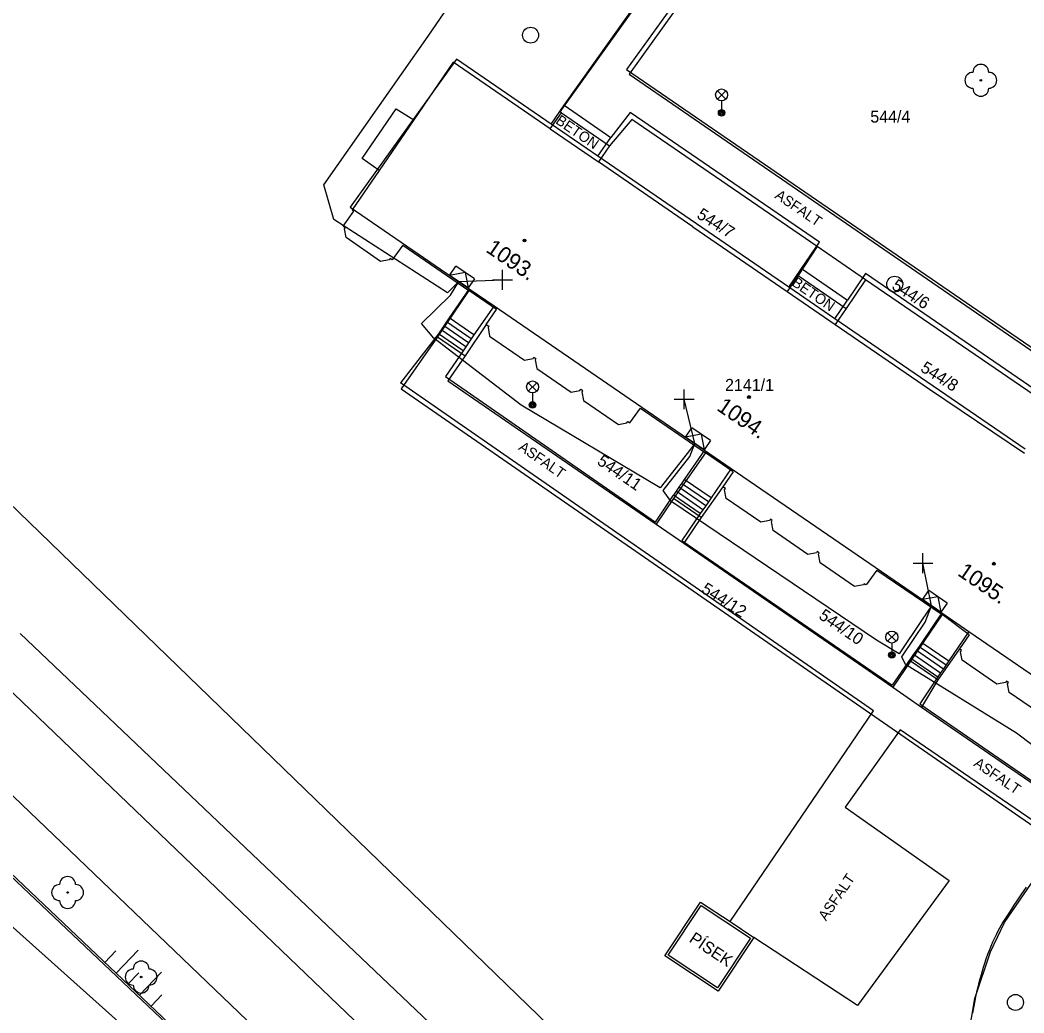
# Model space of a CAD drawing. Extents: x -540150 to -533593, y -1185082 to -1180066.
# Drawn here: x -536687.4 to -536624.5, y -1184506.1 to -1184443.9 of the extents above; entities that cross this region are included whole.
import ezdxf

# ---------------------------------------------------------------- set-up
doc = ezdxf.new("R2010")
doc.units = 0
for name, color, linetype in [('KN_HRAN_K_Ú', 7, 'Continuous'), ('KN_HRAN_PARCEL', 7, 'Continuous'), ('KN_PARC_Č', 7, 'Continuous'), ('KN_VKP_HRAN_', 7, 'Continuous'), ('Vrstva 1', 7, 'Continuous'), ('Vrstva 10', 7, 'Continuous'), ('Vrstva 11', 7, 'Continuous'), ('Vrstva 14', 7, 'Continuous'), ('Vrstva 15', 7, 'Continuous'), ('Vrstva 22', 7, 'Continuous'), ('Vrstva 23', 7, 'Continuous'), ('Vrstva 27', 7, 'Continuous'), ('Vrstva 31', 7, 'Continuous'), ('Vrstva 33', 7, 'Continuous'), ('Vrstva 34', 7, 'Continuous'), ('Vrstva 39', 7, 'Continuous'), ('Vrstva 40', 7, 'Continuous'), ('Vrstva 41', 7, 'Continuous'), ('Vrstva 47', 7, 'Continuous'), ('Vrstva 5', 7, 'Continuous'), ('Vrstva 59', 7, 'Continuous'), ('Vrstva 9', 7, 'Continuous')]:
    doc.layers.add(name, color=color, linetype=linetype)

# ---------------------------------------------------------------- blocks, each defined once
blk = doc.blocks.new('NN800')
at = {"layer": 'Vrstva 1'}
for points in [[(-0.442, 0.442), (0.442, -0.442)], [(-0.442, -0.442), (0.442, 0.442)]]:
    blk.add_lwpolyline(points, dxfattribs=at)
blk = doc.blocks.new('NN630')
at = {"layer": 'Vrstva 9'}
for points in [[(-0.003, -0.7), (-0.703, 0)], [(-0.703, -0.7), (-0.703, 0), (0.697, 0), (0.697, -0.7)], [(-0.003, -0.7), (0.697, 0)], [(-0.703, -0.7), (0.697, -0.7)]]:
    blk.add_lwpolyline(points, dxfattribs=at)

msp = doc.modelspace()

# ---------------------------------------------------------------- linework, layer by layer
at = {"layer": 'KN_HRAN_K_Ú'}
msp.add_line((-536697.202, -1184477.151), (-536639.212, -1184532.701), dxfattribs=at)
at = {"layer": 'KN_HRAN_PARCEL'}
for p, q in [((-536653.562, -1184449.641), (-536639.962, -1184430.591)), ((-536638.172, -1184431.831), (-536649.252, -1184447.281)), ((-536660.272, -1184446.531), (-536662.732, -1184450.131)), ((-536654.192, -1184450.701), (-536660.272, -1184446.531)), ((-536649.252, -1184447.281), (-536620.072, -1184467.331)), ((-536665.982, -1184452.571), (-536663.842, -1184449.451)), ((-536663.842, -1184449.451), (-536662.732, -1184450.131)), ((-536654.192, -1184450.701), (-536653.492, -1184449.691)), ((-536653.492, -1184449.691), (-536653.562, -1184449.641)), ((-536653.492, -1184449.691), (-536650.472, -1184451.761)), ((-536649.082, -1184450.111), (-536650.472, -1184451.761)), ((-536637.462, -1184458.071), (-536649.082, -1184450.111)), ((-536650.472, -1184451.761), (-536651.172, -1184452.781)), ((-536664.912, -1184453.311), (-536665.982, -1184452.571)), ((-536645.252, -1184456.841), (-536651.172, -1184452.781)), ((-536664.912, -1184453.311), (-536666.602, -1184455.791)), ((-536667.162, -1184456.811), (-536666.492, -1184455.861)), ((-536666.602, -1184455.791), (-536666.492, -1184455.861)), ((-536667.042, -1184456.901), (-536667.162, -1184456.811)), ((-536667.092, -1184456.981), (-536667.042, -1184456.901)), ((-536645.252, -1184456.841), (-536639.342, -1184460.891)), ((-536666.992, -1184457.521), (-536667.092, -1184456.981)), ((-536664.822, -1184459.021), (-536666.992, -1184457.521)), ((-536663.422, -1184457.991), (-536664.102, -1184458.921)), ((-536663.422, -1184457.991), (-536659.292, -1184460.831)), ((-536637.462, -1184458.071), (-536638.662, -1184459.901)), ((-536634.422, -1184460.161), (-536637.462, -1184458.071)), ((-536664.222, -1184458.831), (-536664.282, -1184458.911)), ((-536664.102, -1184458.921), (-536664.222, -1184458.831)), ((-536664.282, -1184458.911), (-536664.822, -1184459.021)), ((-536638.662, -1184459.901), (-536639.342, -1184460.891)), ((-536634.422, -1184460.161), (-536635.652, -1184461.961)), ((-536622.662, -1184468.231), (-536634.422, -1184460.161)), ((-536659.292, -1184460.831), (-536661.252, -1184463.741)), ((-536635.652, -1184461.961), (-536636.332, -1184462.961)), ((-536658.202, -1184462.961), (-536659.522, -1184464.931)), ((-536658.202, -1184462.961), (-536658.032, -1184463.081)), ((-536658.032, -1184463.081), (-536658.092, -1184463.161)), ((-536658.092, -1184463.161), (-536657.992, -1184463.701)), ((-536636.332, -1184462.961), (-536630.412, -1184467.031)), ((-536661.252, -1184463.741), (-536663.532, -1184467.001)), ((-536661.252, -1184463.741), (-536659.522, -1184464.931)), ((-536657.992, -1184463.701), (-536655.812, -1184465.201)), ((-536659.522, -1184464.931), (-536660.612, -1184466.491)), ((-536655.812, -1184465.201), (-536655.272, -1184465.091)), ((-536655.272, -1184465.091), (-536655.212, -1184465.011)), ((-536655.212, -1184465.011), (-536655.092, -1184465.101)), ((-536655.092, -1184465.101), (-536655.142, -1184465.181)), ((-536655.142, -1184465.181), (-536655.042, -1184465.721)), ((-536655.042, -1184465.721), (-536652.872, -1184467.211)), ((-536663.532, -1184467.001), (-536622.332, -1184495.521)), ((-536660.612, -1184466.491), (-536647.562, -1184475.491)), ((-536652.872, -1184467.211), (-536652.332, -1184467.111)), ((-536652.332, -1184467.111), (-536652.272, -1184467.031)), ((-536652.272, -1184467.031), (-536652.212, -1184467.071)), ((-536652.212, -1184467.071), (-536652.152, -1184467.121)), ((-536652.152, -1184467.121), (-536652.202, -1184467.201)), ((-536652.202, -1184467.201), (-536652.102, -1184467.741)), ((-536630.412, -1184467.031), (-536624.472, -1184471.041)), ((-536652.102, -1184467.741), (-536649.922, -1184469.231)), ((-536649.202, -1184469.131), (-536648.542, -1184468.211)), ((-536648.542, -1184468.211), (-536644.452, -1184471.021)), ((-536649.922, -1184469.231), (-536649.382, -1184469.131)), ((-536649.382, -1184469.131), (-536649.332, -1184469.051)), ((-536649.332, -1184469.051), (-536649.202, -1184469.131)), ((-536644.452, -1184471.021), (-536646.462, -1184473.881)), ((-536633.292, -1184527.221), (-536690.882, -1184471.461)), ((-536643.372, -1184473.141), (-536644.732, -1184475.071)), ((-536643.212, -1184473.251), (-536643.372, -1184473.141)), ((-536643.272, -1184473.331), (-536643.212, -1184473.251)), ((-536646.462, -1184473.881), (-536647.562, -1184475.491)), ((-536643.172, -1184473.871), (-536643.272, -1184473.331)), ((-536640.992, -1184475.361), (-536643.172, -1184473.871)), ((-536644.732, -1184475.071), (-536645.822, -1184476.681)), ((-536640.392, -1184475.181), (-536640.452, -1184475.261)), ((-536640.272, -1184475.261), (-536640.392, -1184475.181)), ((-536647.562, -1184475.491), (-536645.822, -1184476.681)), ((-536640.452, -1184475.261), (-536640.992, -1184475.361)), ((-536640.322, -1184475.351), (-536640.272, -1184475.261)), ((-536640.222, -1184475.891), (-536640.322, -1184475.351)), ((-536638.052, -1184477.381), (-536640.222, -1184475.891)), ((-536645.822, -1184476.681), (-536632.722, -1184485.711)), ((-536637.512, -1184477.281), (-536638.052, -1184477.381)), ((-536637.452, -1184477.201), (-536637.512, -1184477.281)), ((-536637.392, -1184477.241), (-536637.452, -1184477.201)), ((-536637.332, -1184477.281), (-536637.392, -1184477.241)), ((-536637.382, -1184477.371), (-536637.332, -1184477.281)), ((-536637.282, -1184477.911), (-536637.382, -1184477.371)), ((-536635.112, -1184479.401), (-536637.282, -1184477.911)), ((-536633.712, -1184478.371), (-536634.382, -1184479.301)), ((-536633.712, -1184478.371), (-536629.622, -1184481.141)), ((-536634.562, -1184479.301), (-536635.112, -1184479.401)), ((-536634.512, -1184479.221), (-536634.562, -1184479.301)), ((-536634.382, -1184479.301), (-536634.512, -1184479.221)), ((-536629.622, -1184481.141), (-536631.612, -1184484.071)), ((-536648.792, -1184519.081), (-536687.422, -1184482.341)), ((-536628.542, -1184483.311), (-536629.892, -1184485.251)), ((-536628.422, -1184483.401), (-536628.542, -1184483.311)), ((-536628.472, -1184483.481), (-536628.422, -1184483.401)), ((-536628.372, -1184484.021), (-536628.472, -1184483.481)), ((-536631.612, -1184484.071), (-536632.722, -1184485.711)), ((-536626.202, -1184485.511), (-536628.372, -1184484.021)), ((-536629.892, -1184485.251), (-536630.932, -1184486.951)), ((-536632.722, -1184485.711), (-536630.932, -1184486.951)), ((-536625.652, -1184485.411), (-536626.202, -1184485.511)), ((-536625.602, -1184485.331), (-536625.652, -1184485.411)), ((-536625.472, -1184485.421), (-536625.602, -1184485.331)), ((-536625.532, -1184485.501), (-536625.472, -1184485.421)), ((-536625.432, -1184486.041), (-536625.532, -1184485.501)), ((-536623.252, -1184487.531), (-536625.432, -1184486.041)), ((-536630.932, -1184486.951), (-536621.042, -1184493.761)), ((-536691.382, -1184494.351), (-536675.902, -1184509.001)), ((-536625.722, -1184500.451), (-536622.332, -1184495.521)), ((-536626.592, -1184502.301), (-536625.722, -1184500.451)), ((-536627.582, -1184505.221), (-536626.592, -1184502.301)), ((-536628.102, -1184508.251), (-536627.582, -1184505.221))]:
    msp.add_line(p, q, dxfattribs=at)
at = {"layer": 'KN_VKP_HRAN_'}
for p, q in [((-536662.732, -1184450.131), (-536664.912, -1184453.311)), ((-536654.192, -1184450.701), (-536651.172, -1184452.781)), ((-536638.662, -1184459.901), (-536635.652, -1184461.961)), ((-536657.562, -1184462.021), (-536659.292, -1184460.831)), ((-536639.342, -1184460.891), (-536636.332, -1184462.961)), ((-536658.202, -1184462.961), (-536657.562, -1184462.021)), ((-536642.722, -1184472.211), (-536644.452, -1184471.021)), ((-536642.722, -1184472.211), (-536643.372, -1184473.141)), ((-536644.732, -1184475.071), (-536646.462, -1184473.881)), ((-536627.932, -1184482.421), (-536629.622, -1184481.141)), ((-536627.932, -1184482.421), (-536628.542, -1184483.311)), ((-536629.892, -1184485.251), (-536631.612, -1184484.071))]:
    msp.add_line(p, q, dxfattribs=at)
at = {"layer": 'Vrstva 10'}
for p, q in [((-536647.007, -1184502.544), (-536644.772, -1184499.181)), ((-536646.799, -1184502.502), (-536644.73, -1184499.389)), ((-536644.73, -1184499.389), (-536641.64, -1184501.443)), ((-536641.64, -1184501.443), (-536643.709, -1184504.556)), ((-536641.432, -1184501.401), (-536643.667, -1184504.764)), ((-536643.667, -1184504.764), (-536647.007, -1184502.544)), ((-536643.709, -1184504.556), (-536646.799, -1184502.502))]:
    msp.add_line(p, q, dxfattribs=at)
for points in [[(-536624.359, -1184498.235), (-536624.696, -1184498.726), (-536624.947, -1184499.098), (-536625.135, -1184499.38), (-536625.414, -1184499.807), (-536625.692, -1184500.241), (-536625.814, -1184500.438), (-536625.927, -1184500.631), (-536626.033, -1184500.82), (-536626.132, -1184501.004)], [(-536644.772, -1184499.181), (-536642.922, -1184500.391), (-536641.432, -1184501.401)], [(-536626.311, -1184501.359), (-536626.391, -1184501.529), (-536626.467, -1184501.696), (-536626.537, -1184501.858), (-536626.604, -1184502.016), (-536626.666, -1184502.17), (-536626.781, -1184502.47), (-536626.883, -1184502.753), (-536626.973, -1184503.02), (-536627.053, -1184503.272), (-536627.125, -1184503.509), (-536627.189, -1184503.732), (-536627.246, -1184503.942), (-536627.298, -1184504.139), (-536627.39, -1184504.51), (-536627.465, -1184504.836), (-536627.527, -1184505.121), (-536627.579, -1184505.371), (-536627.665, -1184505.81), (-536627.725, -1184506.138)], [(-536626.132, -1184501.004), (-536626.224, -1184501.183), (-536626.311, -1184501.359)]]:
    msp.add_lwpolyline(points, dxfattribs=at)
at = {"layer": 'Vrstva 11'}
for p, q in [((-536653.322, -1184449.221), (-536639.952, -1184430.391)), ((-536638.212, -1184431.481), (-536649.422, -1184446.991)), ((-536649.422, -1184446.991), (-536620.042, -1184467.151)), ((-536654.136, -1184450.407), (-536653.322, -1184449.221)), ((-536653.322, -1184449.221), (-536650.402, -1184451.241)), ((-536649.192, -1184449.671), (-536650.402, -1184451.241)), ((-536637.312, -1184457.811), (-536649.192, -1184449.671)), ((-536651.208, -1184452.416), (-536650.402, -1184451.241)), ((-536638.447, -1184459.464), (-536637.312, -1184457.811)), ((-536639.244, -1184460.626), (-536638.447, -1184459.464)), ((-536638.447, -1184459.464), (-536635.552, -1184461.451)), ((-536634.432, -1184459.781), (-536635.552, -1184461.451)), ((-536622.492, -1184467.961), (-536634.432, -1184459.781)), ((-536636.349, -1184462.613), (-536635.552, -1184461.451)), ((-536658.971, -1184463.626), (-536660.522, -1184462.561)), ((-536659.311, -1184464.121), (-536660.862, -1184463.056)), ((-536659.141, -1184463.874), (-536660.692, -1184462.809)), ((-536661.202, -1184463.551), (-536663.572, -1184466.631)), ((-536659.651, -1184464.616), (-536661.202, -1184463.551)), ((-536659.481, -1184464.368), (-536661.032, -1184463.303)), ((-536659.651, -1184464.616), (-536660.752, -1184466.221)), ((-536660.752, -1184466.221), (-536647.592, -1184475.361)), ((-536633.922, -1184487.181), (-536663.572, -1184466.631)), ((-536644.108, -1184473.837), (-536645.793, -1184472.681)), ((-536644.447, -1184474.332), (-536646.132, -1184473.176)), ((-536644.277, -1184474.084), (-536645.962, -1184472.928)), ((-536647.592, -1184475.361), (-536646.472, -1184473.671)), ((-536644.787, -1184474.827), (-536646.472, -1184473.671)), ((-536644.617, -1184474.579), (-536646.302, -1184473.423)), ((-536644.787, -1184474.827), (-536645.942, -1184476.511)), ((-536645.942, -1184476.511), (-536632.752, -1184485.591)), ((-536631.075, -1184483.147), (-536629.382, -1184484.308)), ((-536630.906, -1184482.9), (-536629.213, -1184484.061)), ((-536631.585, -1184483.89), (-536632.752, -1184485.591)), ((-536631.585, -1184483.89), (-536629.892, -1184485.051)), ((-536631.415, -1184483.642), (-536629.722, -1184484.803)), ((-536631.245, -1184483.395), (-536629.552, -1184484.556)), ((-536629.892, -1184485.051), (-536631.032, -1184486.751)), ((-536631.032, -1184486.751), (-536620.952, -1184493.691)), ((-536642.922, -1184500.391), (-536633.922, -1184487.181)), ((-536632.252, -1184488.381), (-536635.712, -1184493.221)), ((-536622.192, -1184495.281), (-536632.252, -1184488.381)), ((-536635.712, -1184493.221), (-536629.182, -1184497.831)), ((-536629.182, -1184497.831), (-536634.932, -1184505.661)), ((-536634.932, -1184505.661), (-536641.432, -1184501.401))]:
    msp.add_line(p, q, dxfattribs=at)
for points in [[(-536659.268, -1184460.732), (-536660.522, -1184462.561), (-536660.692, -1184462.809), (-536660.862, -1184463.056), (-536661.032, -1184463.303), (-536661.202, -1184463.551)], [(-536657.716, -1184461.796), (-536658.971, -1184463.626), (-536659.141, -1184463.874), (-536659.311, -1184464.121), (-536659.481, -1184464.368), (-536659.651, -1184464.616)], [(-536644.531, -1184470.842), (-536645.793, -1184472.681), (-536645.962, -1184472.928), (-536646.132, -1184473.176), (-536646.302, -1184473.423), (-536646.472, -1184473.671)], [(-536642.846, -1184471.998), (-536644.108, -1184473.837), (-536644.277, -1184474.084), (-536644.447, -1184474.332), (-536644.617, -1184474.579), (-536644.787, -1184474.827)], [(-536629.641, -1184481.056), (-536630.906, -1184482.9), (-536631.075, -1184483.147), (-536631.245, -1184483.395), (-536631.415, -1184483.642), (-536631.585, -1184483.89)], [(-536627.948, -1184482.218), (-536629.213, -1184484.061), (-536629.382, -1184484.308), (-536629.552, -1184484.556), (-536629.722, -1184484.803), (-536629.892, -1184485.051)]]:
    msp.add_lwpolyline(points, dxfattribs=at)
at = {"layer": 'Vrstva 14'}
for p, q in [((-536695.692, -1184485.041), (-536670.862, -1184508.831)), ((-536673.732, -1184510.911), (-536697.702, -1184488.171))]:
    msp.add_line(p, q, dxfattribs=at)
at = {"layer": 'Vrstva 15'}
for p, q in [((-536682.116, -1184502.958), (-536681.428, -1184502.232)), ((-536681.39, -1184503.646), (-536680.014, -1184502.195)), ((-536680.665, -1184504.334), (-536679.977, -1184503.609)), ((-536679.94, -1184505.022), (-536678.563, -1184503.571)), ((-536679.214, -1184505.71), (-536678.526, -1184504.985))]:
    msp.add_line(p, q, dxfattribs=at)
at = {"layer": 'Vrstva 22'}
for centre in [(-536627.202, -1184447.661), (-536684.442, -1184498.581), (-536679.832, -1184503.881)]:
    msp.add_circle(centre, 0.05, dxfattribs=at)
for centre, start, end in [((-536627.202, -1184447.161), 0, 180), ((-536627.702, -1184447.661), 90, 270), ((-536626.702, -1184447.661), 270, 90), ((-536627.202, -1184448.161), 180, 0), ((-536684.442, -1184498.081), 0, 180), ((-536684.942, -1184498.581), 90, 270), ((-536683.942, -1184498.581), 270, 90), ((-536684.442, -1184499.081), 180, 0), ((-536679.832, -1184503.381), 0, 180), ((-536680.332, -1184503.881), 90, 270), ((-536679.332, -1184503.881), 270, 90), ((-536679.832, -1184504.381), 180, 0)]:
    msp.add_arc(centre, 0.5, start, end, dxfattribs=at)
at = {"layer": 'Vrstva 23'}
msp.add_line((-536699.382, -1184490.491), (-536674.972, -1184512.291), dxfattribs=at)
at = {"layer": 'Vrstva 27'}
for centre in [(-536655.422, -1184444.831), (-536632.602, -1184460.441), (-536625.032, -1184505.471)]:
    msp.add_circle(centre, 0.5, dxfattribs=at)
at = {"layer": 'Vrstva 33'}
for p, q in [((-536643.717, -1184448.841), (-536643.187, -1184448.311)), ((-536643.717, -1184448.311), (-536643.187, -1184448.841)), ((-536643.452, -1184448.951), (-536643.452, -1184449.701)), ((-536655.567, -1184467.151), (-536655.037, -1184466.621)), ((-536655.567, -1184466.621), (-536655.037, -1184467.151)), ((-536655.302, -1184467.261), (-536655.302, -1184468.011)), ((-536633.047, -1184482.831), (-536632.517, -1184482.301)), ((-536633.047, -1184482.301), (-536632.517, -1184482.831)), ((-536632.782, -1184482.941), (-536632.782, -1184483.691))]:
    msp.add_line(p, q, dxfattribs=at)
for centre, radius in [((-536643.452, -1184448.576), 0.375), ((-536643.452, -1184449.701), 0.2), ((-536643.452, -1184449.701), 0.145), ((-536643.452, -1184449.701), 0.0876), ((-536655.302, -1184466.886), 0.375), ((-536655.302, -1184468.011), 0.2), ((-536655.302, -1184468.011), 0.145), ((-536655.302, -1184468.011), 0.0876), ((-536632.782, -1184482.566), 0.375), ((-536632.782, -1184483.691), 0.2), ((-536632.782, -1184483.691), 0.145), ((-536632.782, -1184483.691), 0.0876)]:
    msp.add_circle(centre, radius, dxfattribs=at)
at = {"layer": 'Vrstva 39'}
for centre, radius in [((-536655.802, -1184457.706), 0.09), ((-536655.802, -1184457.706), 0.0398), ((-536641.735, -1184467.516), 0.09), ((-536641.735, -1184467.516), 0.0398), ((-536626.389, -1184477.965), 0.09), ((-536626.389, -1184477.965), 0.0398)]:
    msp.add_circle(centre, radius, dxfattribs=at)
at = {"layer": 'Vrstva 5'}
msp.add_line((-536660.062, -1184446.341), (-536666.732, -1184455.611), dxfattribs=at)
for points in [[(-536620.102, -1184492.261), (-536624.972, -1184488.591), (-536631.932, -1184484.291), (-536632.16, -1184483.804), (-536630.691, -1184481.632), (-536630.287, -1184480.613), (-536630.884, -1184481.458), (-536632.329, -1184483.606), (-536633.732, -1184482.761), (-536646.642, -1184474.041), (-536647.117, -1184473.374), (-536645.451, -1184471.247), (-536645.13, -1184470.43), (-536645.607, -1184471.054), (-536647.3, -1184473.207), (-536656.012, -1184468.021), (-536661.492, -1184463.831), (-536662.262, -1184462.911), (-536660.433, -1184461.138), (-536659.92, -1184460.284), (-536660.628, -1184460.982), (-536667.752, -1184456.391), (-536668.392, -1184454.211), (-536661.852, -1184444.901), (-536655.282, -1184435.291)], [(-536654.136, -1184450.407), (-536660.062, -1184446.341)], [(-536651.208, -1184452.416), (-536654.136, -1184450.407)], [(-536639.244, -1184460.626), (-536651.208, -1184452.416)], [(-536666.732, -1184455.611), (-536659.268, -1184460.732)], [(-536636.349, -1184462.613), (-536639.244, -1184460.626)], [(-536659.268, -1184460.732), (-536657.716, -1184461.796)], [(-536657.716, -1184461.796), (-536644.531, -1184470.842)], [(-536624.433, -1184470.789), (-536636.349, -1184462.613)], [(-536644.531, -1184470.842), (-536642.846, -1184471.998)], [(-536642.846, -1184471.998), (-536629.641, -1184481.056)], [(-536629.641, -1184481.056), (-536627.948, -1184482.218)], [(-536627.948, -1184482.218), (-536621.792, -1184486.441)]]:
    msp.add_lwpolyline(points, dxfattribs=at)
at = {"layer": 'Vrstva 59'}
for points in [[(-536659.92, -1184460.284), (-536657.187, -1184460.169)], [(-536645.13, -1184470.43), (-536645.799, -1184467.661)], [(-536630.287, -1184480.613), (-536630.829, -1184477.925)]]:
    msp.add_lwpolyline(points, dxfattribs=at)

# ---------------------------------------------------------------- block references
at = {"layer": 'Vrstva 31'}
for p, rotation in [((-536659.92, -1184460.283), 145.64415554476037), ((-536645.13, -1184470.429), 145.6441555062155), ((-536630.287, -1184480.612), 145.64415561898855)]:
    msp.add_blockref('NN630', p, dxfattribs=dict(at, rotation=rotation))
at = {"layer": 'Vrstva 34', "rotation": 45}
for p in [(-536657.187, -1184460.168), (-536645.799, -1184467.661), (-536630.829, -1184477.924)]:
    msp.add_blockref('NN800', p, dxfattribs=at)

# ---------------------------------------------------------------- texts
at = {"layer": 'KN_PARC_Č'}
for s, p in [('544/4', (-536634.132, -1184450.311)), ('2141/1', (-536643.235, -1184467.131))]:
    msp.add_text(s, height=0.75, dxfattribs=at).set_placement(p)
for s, rotation, p in [('544/7', 327.6, (-536645.062, -1184456.251)), ('544/6', 327.6, (-536632.842, -1184460.701)), ('544/8', 327.6, (-536631.042, -1184465.861)), ('544/11', 325.40769, (-536651.312, -1184471.685)), ('544/12', 327.6, (-536644.782, -1184479.731)), ('544/10', 325.42101, (-536637.417, -1184481.364))]:
    msp.add_text(s, height=0.75, rotation=rotation, dxfattribs=at).set_placement(p)
at = {"layer": 'Vrstva 40'}
for s, rotation, p in [('BETON', 325.5426, (-536653.907, -1184450.322)), ('ASFALT', 325.58164, (-536640.164, -1184455.003)), ('BETON', 325.5426, (-536639.103, -1184460.48)), ('ASFALT', 325.27471, (-536656.232, -1184470.785)), ('ASFALT', 325.55437, (-536627.7, -1184490.607)), ('ASFALT', 55.73491, (-536636.904, -1184500.403))]:
    msp.add_text(s, height=0.65, rotation=rotation, dxfattribs=at).set_placement(p)
at = {"layer": 'Vrstva 41'}
msp.add_text('PÍSEK', height=0.75, rotation=326.38918, dxfattribs=at).set_placement((-536645.541, -1184501.635))
at = {"layer": 'Vrstva 47'}
for s, p in [('1093.', (-536658.282, -1184458.376)), ('1094.', (-536643.817, -1184468.299)), ('1095.', (-536628.718, -1184478.657))]:
    msp.add_text(s, height=1, rotation=325.54887, dxfattribs=at).set_placement(p)

doc.saveas('drawing.dxf')
